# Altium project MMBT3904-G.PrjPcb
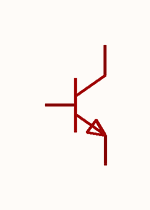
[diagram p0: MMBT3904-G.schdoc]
1 sheet, 1 parts. Net scope: global (net labels, ports and power ports of the same name join across sheets).

## Sheet MMBT3904-G.schdoc
size 127 x 101 mm

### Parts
Q?  mmbt3904-g(range:100-300)  [SOT-23-3_L2.9-W1.3-P1.90-LS2.4-BR]  (value not drawn)

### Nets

Not connected (* = marked no-connect by the designer): Q? 1(B) 2(E) 3(C)

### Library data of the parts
Q? = mmbt3904-g(range:100-300): 晶体管类型:NPN;集电极电流(Ic):200mA;集射极击穿电压(Vceo):40V;耗散功率(Pd):200mW;直流电流增益(hFE):100;; Manufacturer: CJ(江苏长电/长晶); AddInBom: yes; ModelId: c62791f0466c4ae2a892c056b845b0ca; ModelName: SOT-23-3P_L2.9-W1.3-H1.0-LS2.4-P0.95; ModelTransform: 98.425,114.173,0,180,0,0,0.0005,-0.0005,0; type: NPN; Current - Collector(Ic): 200mA; Collector - Emitter Voltage VCEO: 40V; Pd - Power Dissipation: 200mW; DC Current Gain: 100; Transition frequency(fT): 300MHz; Current - Collector Cutoff: 100nA; Vce Saturation(VCE(sat)): 300mV; Emitter-Base Voltage(Vebo): 6V; Number: 1个NPN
